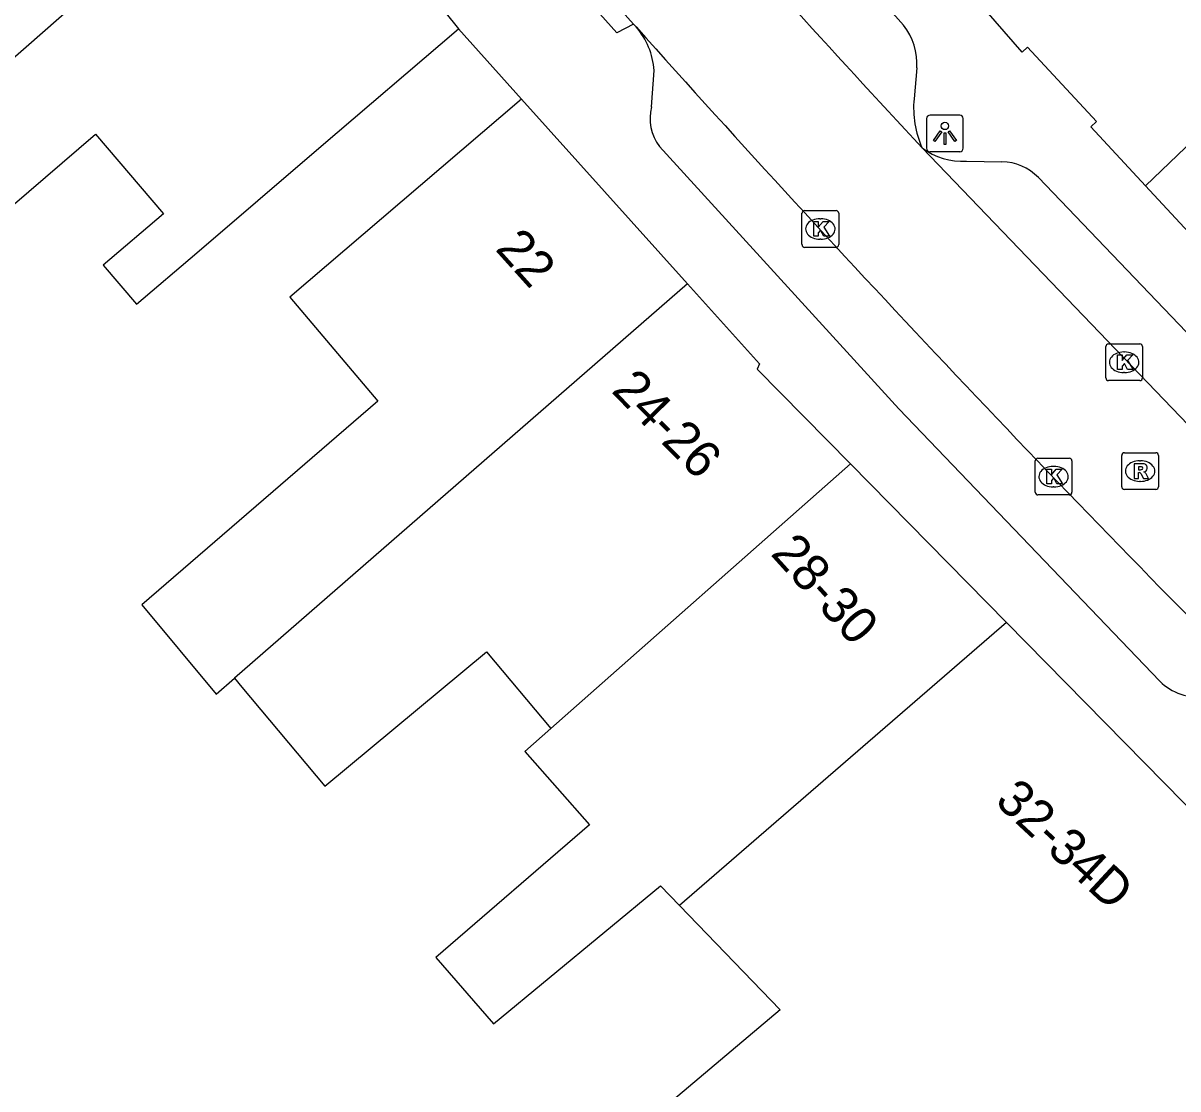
# Model space of a CAD drawing. Extents: x 160664 to 161506, y 382245 to 383288.
# Drawn here: x 160883.81 to 160915.24, y 383116.46 to 383145.46 of the extents above; entities that cross this region are included whole.
import ezdxf

# ---------------------------------------------------------------- set-up
doc = ezdxf.new("R2010")
doc.units = 0
for name, color, linetype in [('IMGEO_Kolk', 7, 'Continuous'), ('IMGEO_Lichtpunt', 7, 'Continuous'), ('IMGEO_Pand', 7, 'Continuous'), ('IMGEO_Pand_nummerreeks', 7, 'Continuous'), ('IMGEO_Rijbaan_lokaal_open', 7, 'Continuous'), ('IMGEO_Rioolput', 7, 'Continuous'), ('IMGEO_Voetpad_open', 7, 'Continuous')]:
    doc.layers.add(name, color=color, linetype=linetype)

msp = doc.modelspace()

# ---------------------------------------------------------------- linework, layer by layer
at = {"layer": 'IMGEO_Kolk'}
for p, q in [((160905.011, 383139.434), (160905.011, 383140.286)), ((160905.086, 383140.36), (160905.938, 383140.36)), ((160906.012, 383140.286), (160906.012, 383139.434)), ((160905.499, 383140.14), (160905.524, 383140.14)), ((160905.522, 383139.58), (160905.497, 383139.58)), ((160905.938, 383139.36), (160905.086, 383139.36)), ((160913.356, 383136.732), (160914.208, 383136.732)), ((160913.281, 383135.806), (160913.281, 383136.658)), ((160913.769, 383136.512), (160913.794, 383136.512)), ((160914.282, 383136.658), (160914.282, 383135.806)), ((160913.792, 383135.952), (160913.767, 383135.952)), ((160914.208, 383135.732), (160913.356, 383135.732)), ((160911.435, 383133.62), (160912.287, 383133.62)), ((160911.36, 383132.694), (160911.36, 383133.546)), ((160911.848, 383133.4), (160911.873, 383133.4)), ((160912.361, 383133.546), (160912.361, 383132.694)), ((160911.871, 383132.84), (160911.846, 383132.84)), ((160912.287, 383132.62), (160911.435, 383132.62))]:
    msp.add_line(p, q, dxfattribs=at)
for points in [[(160905.011, 383139.434), (160905.011, 383140.286)], [(160905.086, 383140.36), (160905.938, 383140.36)], [(160906.012, 383140.286), (160906.012, 383139.434)], [(160905.332, 383140.06), (160905.455, 383140.06), (160905.455, 383139.909), (160905.585, 383140.06), (160905.749, 383140.06), (160905.603, 383139.909), (160905.756, 383139.66), (160905.604, 383139.66), (160905.519, 383139.824), (160905.455, 383139.757), (160905.455, 383139.66), (160905.332, 383139.66), (160905.332, 383140.06)], [(160905.938, 383139.36), (160905.086, 383139.36)], [(160913.356, 383136.732), (160914.208, 383136.732)], [(160913.281, 383135.806), (160913.281, 383136.658)], [(160913.602, 383136.432), (160913.725, 383136.432), (160913.725, 383136.281), (160913.855, 383136.432), (160914.019, 383136.432), (160913.873, 383136.281), (160914.026, 383136.032), (160913.874, 383136.032), (160913.789, 383136.196), (160913.725, 383136.129), (160913.725, 383136.032), (160913.602, 383136.032), (160913.602, 383136.432)], [(160914.282, 383136.658), (160914.282, 383135.806)], [(160914.208, 383135.732), (160913.356, 383135.732)], [(160911.435, 383133.62), (160912.287, 383133.62)], [(160911.36, 383132.694), (160911.36, 383133.546)], [(160911.681, 383133.32), (160911.804, 383133.32), (160911.804, 383133.169), (160911.934, 383133.32), (160912.098, 383133.32), (160911.952, 383133.169), (160912.105, 383132.92), (160911.953, 383132.92), (160911.868, 383133.084), (160911.804, 383133.017), (160911.804, 383132.92), (160911.681, 383132.92), (160911.681, 383133.32)], [(160912.361, 383133.546), (160912.361, 383132.694)], [(160912.287, 383132.62), (160911.435, 383132.62)]]:
    msp.add_lwpolyline(points, dxfattribs=at)
for centre, start, end in [((160905.088, 383140.284), 91.552, 178.448), ((160905.088, 383140.284), 91.552, 178.448), ((160905.936, 383140.284), 1.552, 88.448), ((160905.936, 383140.284), 1.552, 88.448), ((160905.088, 383139.436), 181.552, 268.448), ((160905.088, 383139.436), 181.552, 268.448), ((160905.936, 383139.436), 271.552, 358.448), ((160905.936, 383139.436), 271.552, 358.448), ((160913.358, 383136.656), 91.552, 178.448), ((160913.358, 383136.656), 91.552, 178.448), ((160914.206, 383136.656), 1.552, 88.448), ((160914.206, 383136.656), 1.552, 88.448), ((160913.358, 383135.808), 181.552, 268.448), ((160913.358, 383135.808), 181.552, 268.448), ((160914.206, 383135.808), 271.552, 358.448), ((160914.206, 383135.808), 271.552, 358.448), ((160911.437, 383133.544), 91.552, 178.448), ((160911.437, 383133.544), 91.552, 178.448), ((160912.285, 383133.544), 1.552, 88.448), ((160912.285, 383133.544), 1.552, 88.448), ((160911.437, 383132.696), 181.552, 268.448), ((160911.437, 383132.696), 181.552, 268.448), ((160912.285, 383132.696), 271.552, 358.448), ((160912.285, 383132.696), 271.552, 358.448)]:
    msp.add_arc(centre, 0.0765, start, end, dxfattribs=at)
for centre, major_axis, ratio, start_param, end_param in [((160905.498, 383139.86), (-0.387, 0.002), 0.722429, 4.712389, 7.853982), ((160905.523, 383139.86), (-0.39, 0.002), 0.717154, 1.570796, 4.712389), ((160913.768, 383136.232), (-0.387, 0.002), 0.722429, 4.712389, 7.853982), ((160913.793, 383136.232), (-0.39, 0.002), 0.717154, 1.570796, 4.712389), ((160911.847, 383133.12), (-0.387, 0.002), 0.722429, 4.712389, 7.853982), ((160911.872, 383133.12), (-0.39, 0.002), 0.717154, 1.570796, 4.712389)]:
    msp.add_ellipse(centre, major_axis=major_axis, ratio=ratio, start_param=start_param, end_param=end_param, dxfattribs=at)
at = {"layer": 'IMGEO_Lichtpunt'}
for p, q in [((160908.403, 383142.865), (160908.403, 383142.058)), ((160908.403, 383142.865), (160908.403, 383142.058)), ((160909.305, 383142.96), (160908.497, 383142.96)), ((160909.305, 383142.96), (160908.497, 383142.96)), ((160909.399, 383142.058), (160909.399, 383142.865)), ((160909.399, 383142.058), (160909.399, 383142.865)), ((160908.497, 383141.964), (160909.305, 383141.964)), ((160908.497, 383141.964), (160909.305, 383141.964))]:
    msp.add_line(p, q, dxfattribs=at)
for points in [[(160908.777, 383142.529), (160908.816, 383142.501), (160908.628, 383142.239), (160908.59, 383142.266), (160908.777, 383142.529)], [(160908.879, 383142.481), (160908.926, 383142.481), (160908.926, 383142.159), (160908.879, 383142.159), (160908.879, 383142.481)], [(160908.989, 383142.501), (160909.027, 383142.528), (160909.214, 383142.266), (160909.175, 383142.238), (160908.989, 383142.501)]]:
    msp.add_lwpolyline(points, dxfattribs=at)
msp.add_circle((160908.902, 383142.663), 0.0994, dxfattribs=at)
for centre, start, end in [((160908.497, 383142.865), 90, 180), ((160908.497, 383142.865), 90, 180), ((160909.305, 383142.865), 0, 90), ((160909.305, 383142.865), 0, 90), ((160908.497, 383142.058), 180, 270), ((160908.497, 383142.058), 180, 270), ((160909.305, 383142.058), 270, 0), ((160909.305, 383142.058), 270, 360)]:
    msp.add_arc(centre, 0.0946, start, end, dxfattribs=at)
at = {"layer": 'IMGEO_Pand'}
for points in [[(160890.838, 383150.912), (160879.818, 383141.245)], [(160890.838, 383150.912), (160893.67, 383147.6), (160893.76, 383147.677), (160895.66, 383145.307)], [(160914.367, 383141.037), (160912.875, 383142.644), (160913.028, 383142.786), (160911.152, 383144.808), (160911.004, 383144.676), (160907.392, 383148.829)], [(160879.818, 383141.245), (160881.749, 383138.988), (160885.78, 383142.436), (160887.628, 383140.276), (160885.986, 383138.872), (160886.895, 383137.81), (160888.536, 383139.214), (160891.861, 383142.058), (160895.66, 383145.307)], [(160914.367, 383141.037), (160917.855, 383144.386)], [(160897.371, 383143.39), (160893.567, 383140.138), (160891.067, 383138), (160893.459, 383135.169), (160887.038, 383129.632), (160889.061, 383127.199), (160889.559, 383127.633)], [(160897.371, 383143.39), (160901.89, 383138.37)], [(160920.779, 383134.126), (160920.569, 383134.352), (160914.367, 383141.037)], [(160901.89, 383138.37), (160889.559, 383127.633)], [(160901.89, 383138.37), (160903.854, 383136.188), (160903.793, 383136.048), (160906.332, 383133.466)], [(160898.171, 383126.267), (160906.332, 383133.466)], [(160906.332, 383133.466), (160910.58, 383129.146)], [(160910.58, 383129.146), (160901.674, 383121.447)], [(160910.58, 383129.146), (160916.474, 383123.152), (160916.373, 383123.023), (160919.466, 383120.156)], [(160889.559, 383127.633), (160889.765, 383127.387), (160892.018, 383124.697), (160896.422, 383128.353), (160898.171, 383126.267)], [(160898.171, 383126.267), (160897.466, 383125.634), (160899.226, 383123.638), (160895.042, 383120.03), (160896.614, 383118.226), (160901.159, 383121.98), (160901.674, 383121.447)], [(160901.674, 383121.447), (160904.415, 383118.611), (160900.01, 383114.885), (160902.622, 383112.091), (160898.826, 383108.199), (160898.705, 383108.319), (160893.163, 383102.485)]]:
    msp.add_lwpolyline(points, dxfattribs=at)
at = {"layer": 'IMGEO_Rijbaan_lokaal_open'}
for points in [[(160897.95, 383148.212), (160900.424, 383145.438)], [(160900.495, 383145.362), (160900.424, 383145.438)], [(160920.788, 383129.051), (160908.282, 383142.065)]]:
    msp.add_lwpolyline(points, dxfattribs=at)
for centre, radius, start, end in [((161286.435, 383492.874), 515.816, 220.43448, 222.85184), ((161242.258, 383450.551), 458.195, 221.76429, 224.98305)]:
    msp.add_arc(centre, radius, start, end, dxfattribs=at)
at = {"layer": 'IMGEO_Rioolput'}
for p, q in [((160913.715, 383132.844), (160913.715, 383133.696)), ((160913.79, 383133.77), (160914.642, 383133.77)), ((160914.716, 383133.696), (160914.716, 383132.844)), ((160914.203, 383133.55), (160914.228, 383133.55)), ((160914.226, 383132.99), (160914.201, 383132.99)), ((160914.642, 383132.77), (160913.79, 383132.77))]:
    msp.add_line(p, q, dxfattribs=at)
for points in [[(160913.715, 383132.844), (160913.715, 383133.696)], [(160913.79, 383133.77), (160914.642, 383133.77)], [(160914.716, 383133.696), (160914.716, 383132.844)], [(160914.304, 383133.468), (160914.052, 383133.47), (160914.052, 383133.07)], [(160914.23, 383133.389), (160914.176, 383133.389), (160914.176, 383133.308)], [(160914.176, 383133.308), (160914.228, 383133.308)], [(160914.052, 383133.07), (160914.176, 383133.07), (160914.176, 383133.232), (160914.187, 383133.232)], [(160914.234, 383133.203), (160914.305, 383133.07), (160914.445, 383133.07), (160914.38, 383133.196)], [(160914.642, 383132.77), (160913.79, 383132.77)]]:
    msp.add_lwpolyline(points, dxfattribs=at)
for centre, radius, start, end in [((160913.792, 383133.694), 0.0765, 91.552, 178.448), ((160913.792, 383133.694), 0.0765, 91.552, 178.448), ((160914.64, 383133.694), 0.0765, 1.552, 88.448), ((160914.64, 383133.694), 0.0765, 1.552, 88.448), ((160914.212, 383133.497), 0.19, 274.7715, 282.9687), ((160914.236, 383133.293), 0.0964, 77.0061, 93.1865), ((160914.25, 383133.35), 0.0378, 276.6634, 79.6772), ((160914.303, 383133.358), 0.109, 350.3612, 89.416), ((160914.301, 383133.358), 0.112, 277.5842, 350.9817), ((160914.186, 383133.179), 0.0533, 26.0293, 88.6989), ((160914.285, 383133.143), 0.108, 29.5134, 73.7905), ((160913.792, 383132.846), 0.0765, 181.552, 268.448), ((160913.792, 383132.846), 0.0765, 181.552, 268.448), ((160914.64, 383132.846), 0.0765, 271.552, 358.448), ((160914.64, 383132.846), 0.0765, 271.552, 358.448)]:
    msp.add_arc(centre, radius, start, end, dxfattribs=at)
for centre, major_axis, ratio, start_param, end_param in [((160914.202, 383133.27), (-0.387, 0.002), 0.722429, 4.712389, 7.853982), ((160914.227, 383133.27), (-0.39, 0.002), 0.717154, 1.570796, 4.712389)]:
    msp.add_ellipse(centre, major_axis=major_axis, ratio=ratio, start_param=start_param, end_param=end_param, dxfattribs=at)
at = {"layer": 'IMGEO_Voetpad_open'}
for points in [[(160897.051, 383157.501), (160907.774, 383145.409)], [(160900.424, 383145.438), (160899.972, 383145.196), (160897.576, 383147.881), (160897.95, 383148.212)], [(160895.66, 383145.307), (160897.371, 383143.39)], [(160900.915, 383143.185), (160900.988, 383144.175)], [(160908.134, 383144.243), (160908.061, 383143.405)], [(160914.749, 383127.551), (160907.65, 383134.961), (160901.135, 383142.107)], [(160909.489, 383141.709), (160910.454, 383141.688)], [(160911.446, 383141.26), (160919.692, 383132.649)]]:
    msp.add_lwpolyline(points, dxfattribs=at)
for centre, radius, start, end in [((160898.902, 383144.005), 2.093, 4.6714, 40.438), ((160906.494, 383144.375), 1.645, 355.3863, 38.9296), ((160910.785, 383143.166), 2.735, 174.9872, 203.7433), ((160902.105, 383142.866), 1.232, 165.0148, 218.0544), ((160909.382, 383143.571), 1.865, 233.8506, 273.2829), ((160910.436, 383140.282), 1.406, 44.0636, 89.2607), ((160915.857, 383128.708), 1.602, 226.2473, 274.9352)]:
    msp.add_arc(centre, radius, start, end, dxfattribs=at)

# ---------------------------------------------------------------- texts
at = {"layer": 'IMGEO_Pand_nummerreeks'}
for s, rotation, p in [('22', 311.9919, (160896.637, 383139.302)), ('24-26', 314.5186, (160899.794, 383135.437)), ('28-30', 312.0916, (160904.133, 383131.007)), ('32-34D', 317.17, (160910.232, 383124.243))]:
    msp.add_text(s, height=1, rotation=rotation, dxfattribs=at).set_placement(p)

doc.saveas('drawing.dxf')
